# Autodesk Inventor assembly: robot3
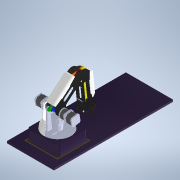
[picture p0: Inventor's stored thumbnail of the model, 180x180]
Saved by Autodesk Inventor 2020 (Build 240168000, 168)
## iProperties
Created: 2017-09
Part Number: robot3
Document SubType Name: Assembly
Designer: bruno
Sending System: SolidWorks 2016
Last Author: Prof
Last Saved: 2018-10-31
Author: bruno
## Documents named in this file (11)
- C:\Users\bruno\Documents\Systèmes\Mallette Bras robotisé (273265)\Dossier ressources\Maquette Dobot SW2016\robot3.iam
- C:\Users\bruno\Documents\Systèmes\Mallette Bras robotisé (273265)\Dossier ressources\Maquette Dobot SW2016\base^robot.iam
- C:\Users\bruno\Documents\Systèmes\Mallette Bras robotisé (273265)\Dossier ressources\Maquette Dobot SW2016\plateforme^robot.iam
- C:\Users\bruno\Documents\Systèmes\Mallette Bras robotisé (273265)\Dossier ressources\Maquette Dobot SW2016\bras inférieur^robot.iam
- C:\Users\bruno\Documents\Systèmes\Mallette Bras robotisé (273265)\Dossier ressources\Maquette Dobot SW2016\manivelle inférieure^robot.iam
- C:\Users\bruno\Documents\Systèmes\Mallette Bras robotisé (273265)\Dossier ressources\Maquette Dobot SW2016\biellette gauche^robot.iam
- C:\Users\bruno\Documents\Systèmes\Mallette Bras robotisé (273265)\Dossier ressources\Maquette Dobot SW2016\biellette droite^robot.iam
- C:\Users\bruno\Documents\Systèmes\Mallette Bras robotisé (273265)\Dossier ressources\Maquette Dobot SW2016\bras supérieur^robot.iam
- C:\Users\bruno\Documents\Systèmes\Mallette Bras robotisé (273265)\Dossier ressources\Maquette Dobot SW2016\basculeur^robot.iam
- C:\Users\bruno\Documents\Systèmes\Mallette Bras robotisé (273265)\Dossier ressources\Maquette Dobot SW2016\biellette avant^robot.iam
- C:\Users\bruno\Documents\Systèmes\Mallette Bras robotisé (273265)\Dossier ressources\Maquette Dobot SW2016\Stylo.iam
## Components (10 placed, 10 different names)
1. base:1 [sub-assembly] — Placage:4, Affleurement:1, Angle:1
2. plateforme:1 [sub-assembly] — Placage:3, Placage:4, Affleurement:1, Placage:5, Placage:6, Placage:7, Placage:8
3. bras inférieur:1 [sub-assembly] — Placage:7, Placage:8, Placage:9, Placage:10, Angle:1
4. manivelle inférieure:1 [sub-assembly] — Placage:1, Placage:2, Placage:3
5. biellette gauche:1 [sub-assembly] — Placage:5, Placage:6, Placage:11, Placage:16
6. biellette droite:1 [sub-assembly] — Placage:1, Placage:2, Placage:20, Placage:21
7. bras supérieur:1 [sub-assembly] — Placage:9, Placage:10, Placage:12, Placage:17, Placage:19, Placage:20, Placage:21
8. basculeur:1 [sub-assembly] — Placage:11, Placage:12, Placage:13, Placage:14, Placage:16
9. biellette avant:1 [sub-assembly] — Placage:13, Placage:14, Placage:18
10. Stylo:1 [sub-assembly] — Placage:17, Placage:18, Placage:19
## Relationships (22: Mate 20, Flush 1, Angle 1)
- Placage:1 [Mate]: manivelle inférieure:1 ↔ biellette droite:1
- Placage:2 [Mate]: manivelle inférieure:1 ↔ biellette droite:1
- Placage:3 [Mate]: plateforme:1 ↔ manivelle inférieure:1
- Placage:4 [Mate]: base:1 ↔ plateforme:1
- Affleurement:1 [Flush]: base:1 ↔ plateforme:1
- Placage:5 [Mate]: plateforme:1 ↔ biellette gauche:1
- Placage:6 [Mate]: plateforme:1 ↔ biellette gauche:1
- Placage:7 [Mate]: plateforme:1 ↔ bras inférieur:1
- Placage:8 [Mate]: plateforme:1 ↔ bras inférieur:1
- Placage:9 [Mate]: bras inférieur:1 ↔ bras supérieur:1
- Placage:10 [Mate]: bras inférieur:1 ↔ bras supérieur:1
- Placage:11 [Mate]: biellette gauche:1 ↔ basculeur:1
- Placage:12 [Mate]: bras supérieur:1 ↔ basculeur:1
- Placage:13 [Mate]: basculeur:1 ↔ biellette avant:1
- Placage:14 [Mate]: basculeur:1 ↔ biellette avant:1
- Placage:16 [Mate]: biellette gauche:1 ↔ basculeur:1
- Placage:17 [Mate]: bras supérieur:1 ↔ Stylo:1
- Placage:18 [Mate]: biellette avant:1 ↔ Stylo:1
- Placage:19 [Mate]: bras supérieur:1 ↔ Stylo:1
- Placage:20 [Mate]: biellette droite:1 ↔ bras supérieur:1
- Placage:21 [Mate]: biellette droite:1 ↔ bras supérieur:1
- Angle:1: base:1 ↔ bras inférieur:1
